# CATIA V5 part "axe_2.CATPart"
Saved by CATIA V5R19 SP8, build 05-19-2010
Part number: axe_2
Bounding box of the stored display mesh (mm): x -135 to 0, y -4.999 to 4.999, z -4.999 to 4.999
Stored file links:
  C:\Users\ThinkMotion\Desktop\EU_thinkMotion\iao\IAO_MMS_Groupe3\avercruysse\IAO_vercruysse\IAO_vercruysse\axe_2.CATPart
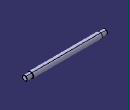
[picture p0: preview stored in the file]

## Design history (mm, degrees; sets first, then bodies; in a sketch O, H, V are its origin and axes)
Body1 (main body)
  Sketch1 on zx-plane, origin (0, 0, 0), H (-1, 0, 0), V (0, 0, 1)
    axis line L1 (-15.7762, 0) -> (635.6097, 0)
    point P1 (-15.7762, 0)
    line L2 (0, 0) -> (0, 4)
    line L3 (0, 4) -> (10, 4)
    line L4 (10, 4) -> (10, 5)
    line L5 (10, 5) -> (125, 5)
    line L6 (125, 5) -> (125, 4)
    line L7 (125, 4) -> (135, 4)
    line L8 (135, 4) -> (135, 0)
    point P9 (135, 0)
    distance L3 L1 = 4
    length L3 = 10
    length L5 = 115
    distance L1 L7 = 4
    length L7 = 10
    distance P1 L5 = 5
    coincidence: P1 H, P9 L1
    horizontal: L1 H, L3 H, L5 H, L7 H
    vertical: L2 V, L4 V, L6 V, L8 V
  Shaft1: profile Sketch1, axis Sketch1.L1, angle 360
  Chamfer1: length 0.5, angle 45, on edge [face of Shaft1 from Sketch1.L2 | face of Shaft1 from Sketch1.L3]; edge [face of Shaft1 from Sketch1.L7 | face of Shaft1 from Sketch1.L8]
  Thread1: "M8", diameter 8, depth 10, pitch 1.25, on face of Shaft1 from Sketch1.L3, from face of Shaft1 from Sketch1.L2
  Thread2: "M8", diameter 8, depth 10, pitch 1.25, on face of Shaft1 from Sketch1.L7, from face of Shaft1 from Sketch1.L8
